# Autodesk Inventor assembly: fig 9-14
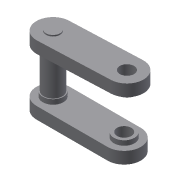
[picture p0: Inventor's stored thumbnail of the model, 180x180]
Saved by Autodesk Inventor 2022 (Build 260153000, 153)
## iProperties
Created: 2002-01
Part Number: fig 9-14
Document SubType Name: Assembly
Designer: ***
Control State: 0
Master: False
Checked Out: False
Shininess: 64.0
Length Units: 11269
Angle Units: 11279
Time Units: 11290
Mass Units: 11283
Length Display Precision: 3
Angle Display Precision: 2
Density: 0.0
Volumn: 0.0
Area: 0.0
PropertySet Name: Model Information
Author: ***
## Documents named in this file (3)
- D:\PROJECTS_2021\Resources\Part Files\c09_Inv_2022_prt\fig 9-14.iam
- D:\PROJECTS_2021\Resources\Part Files\c09_Inv_2022_prt\Part5.ipt
- D:\PROJECTS_2021\Resources\Part Files\c09_Inv_2022_prt\Part6.ipt
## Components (3 placed, 2 different names)
1. Part5:1 — Insert:1
2. Part6:1 — Insert:1, Insert:2
3. Part5:2 — Insert:2
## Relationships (2: Insert 2)
- Insert:1: Part5:1 ↔ Part6:1
- Insert:2: Part6:1 ↔ Part5:2
